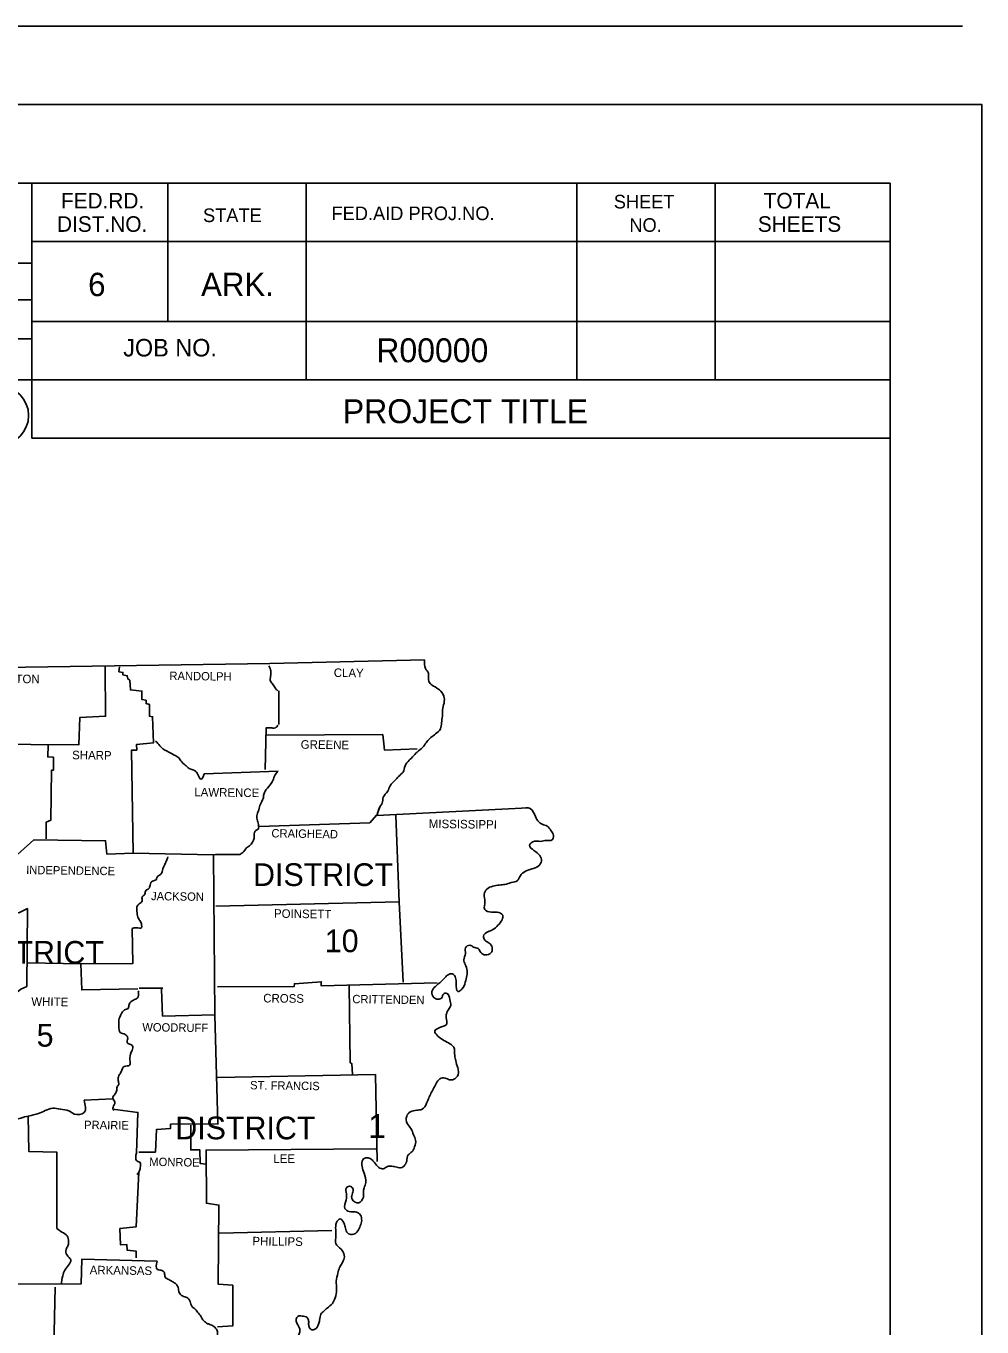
# Model space of a CAD drawing. Extents: x 23481 to 28196, y 1325020 to 1327623.
# Drawn here: x 26612 to 27092, y 1326929 to 1327582 of the extents above; entities that cross this region are included whole.
import ezdxf

# ---------------------------------------------------------------- set-up
doc = ezdxf.new("R2010")
doc.units = 0
doc.layers.add('S_ELECTRIC_UTILITIES_ANNOT', color=7, linetype='Continuous')
doc.layers.add('S_PRIMARY_CTL_ANNOT', color=7, linetype='Continuous')

msp = doc.modelspace()

# ---------------------------------------------------------------- linework, layer by layer
at = {"layer": 'S_ELECTRIC_UTILITIES_ANNOT'}
for p, q in [((27081.89, 1327581.68), (23572.11, 1327581.68)), ((27081.89, 1327542.3), (23808.34, 1327542.3)), ((23883.86, 1327502.83), (27045.67, 1327502.83)), ((26614.82, 1327502.83), (26614.82, 1327374.84)), ((26683.21, 1327502.83), (26683.21, 1327433.46)), ((26752.57, 1327502.83), (26752.57, 1327404.15)), ((26888.38, 1327502.83), (26888.38, 1327404.15)), ((26957.74, 1327502.83), (26957.74, 1327404.15)), ((27045.67, 1325448.4), (27045.67, 1327502.83)), ((27045.67, 1327473.52), (26614.82, 1327473.52)), ((27045.67, 1327473.78), (27045.67, 1327473.78)), ((26223.04, 1327462.77), (26614.82, 1327462.77)), ((26223.04, 1327444.21), (26614.82, 1327444.21)), ((27045.67, 1327433.46), (26614.82, 1327433.46)), ((26223.04, 1327424.67), (26614.82, 1327424.67)), ((27045.67, 1327404.15), (26223.04, 1327404.15)), ((26614.82, 1327374.84), (27045.67, 1327374.84)), ((26788, 1327185.58), (26789.2, 1327189.28)), ((26788.3, 1327186.78), (26789.5, 1327189.68)), ((26668.8, 1327098.98), (26680.7, 1327098.98))]:
    msp.add_line(p, q, dxfattribs=at)
for points in [[(26263.4, 1327259.08), (26425.1, 1327258.98), (26567, 1327259.28), (26734.4, 1327261.88), (26812, 1327263.68)], [(26651.7, 1327260.18), (26651.9, 1327235.38), (26638.9, 1327234.68), (26638.5, 1327221.08), (26566.2, 1327221.48)], [(26658.9, 1327260.08), (26658.6, 1327257.68), (26660.6, 1327257.38), (26660.5, 1327256.18), (26662.8, 1327255.68), (26663, 1327254.08), (26664.1, 1327253.38), (26664.4, 1327248.58), (26670.1, 1327247.98), (26670.1, 1327243.68), (26672.2, 1327243.38), (26672.2, 1327241.68), (26674, 1327241.18), (26673.9, 1327235.38), (26675.5, 1327235.08), (26675.9, 1327221.98), (26667.4, 1327221.18), (26667.5, 1327218.38), (26664.9, 1327218.28), (26665.8, 1327166.68), (26706.1, 1327165.78), (26706.8, 1327085.58), (26680.5, 1327084.88), (26680, 1327098.38)], [(26738.8, 1327248.08), (26738.8, 1327231.18)], [(26732, 1327208.68), (26732.5, 1327229.58), (26732.5, 1327225.88), (26791, 1327226.18), (26791.8, 1327218.38), (26808.3, 1327218.98)], [(26623.1, 1327220.78), (26622.9, 1327214.98), (26625.7, 1327214.78), (26625.8, 1327208.38), (26624.8, 1327208.38), (26624.4, 1327183.18), (26622.1, 1327182.18), (26622.1, 1327173.78)], [(26701.4, 1327206.48), (26738.5, 1327207.78)], [(26729, 1327180.08), (26784.5, 1327181.88), (26787.8, 1327185.68)], [(26788, 1327185.58), (26863.9, 1327189.48)], [(26797.6, 1327185.48), (26799.3, 1327142.18), (26801.3, 1327101.88)], [(26604.5, 1327163.08), (26615.9, 1327173.38), (26651.9, 1327172.88), (26652.6, 1327166.18), (26665.7, 1327166.68)], [(26719.2, 1327165.98), (26707, 1327165.98), (26706.1, 1327165.78)], [(26799.3, 1327142.18), (26707.2, 1327140.08)], [(26556.9, 1327137.08), (26608.3, 1327136.78), (26612.7, 1327138.88), (26612.4, 1327099.78), (26609.4, 1327098.48), (26606.7, 1327096.18), (26605.8, 1327095.28), (26605.7, 1327084.08), (26573, 1327084.08)], [(26665.3, 1327128.88), (26665.5, 1327111.28), (26639.5, 1327111.18), (26612.8, 1327111.68)], [(26639.5, 1327111.18), (26639.9, 1327098.08), (26668, 1327098.58)], [(26708, 1327099.58), (26746.6, 1327099.78), (26746.7, 1327101.18), (26760.1, 1327102.18), (26760.1, 1327100.08), (26818.3, 1327101.68)], [(26774.1, 1327100.08), (26774.6, 1327061.58), (26775.5, 1327060.98), (26775.8, 1327055.78)], [(26774.1, 1327100.08), (26774.6, 1327061.58), (26775.5, 1327060.98), (26775.8, 1327055.78)], [(26774.1, 1327100.08), (26774.6, 1327061.58), (26775.5, 1327060.98), (26775.8, 1327055.78)], [(26774.1, 1327100.08), (26774.6, 1327061.58), (26775.5, 1327060.98), (26775.8, 1327055.78)], [(26774.1, 1327100.08), (26774.6, 1327061.58), (26775.5, 1327060.98), (26775.8, 1327055.78)], [(26668.8, 1327097.28), (26668.3, 1327097.18)], [(26706.8, 1327085.58), (26708.3, 1327030.78), (26684.5, 1327030.68), (26684.4, 1327028.48), (26677.5, 1327028.08), (26676.9, 1327016.68), (26668.5, 1327016.68)], [(26708, 1327054.08), (26787.4, 1327055.68)], [(26787.4, 1327055.68), (26788.2, 1327011.88)], [(26787.4, 1327055.68), (26788.2, 1327011.88)], [(26787.4, 1327055.68), (26788.2, 1327011.88)], [(26787.4, 1327055.68), (26788.2, 1327011.88)], [(26787.4, 1327055.68), (26788.2, 1327011.88)], [(26787.4, 1327055.68), (26788.2, 1327011.88)], [(26787.4, 1327055.68), (26788.2, 1327011.88)], [(26787.4, 1327055.68), (26788.2, 1327011.88)], [(26641.1, 1327042.68), (26655.6, 1327043.38)], [(26613.1, 1327034.88), (26613.3, 1327016.98), (26627.4, 1327016.68), (26627.5, 1326978.28)], [(26655.6, 1327038.18), (26668.1, 1327036.58), (26667.4, 1327016.18)], [(26694.7, 1327030.18), (26694.6, 1327017.78), (26699.2, 1327017.78), (26699.4, 1327010.88), (26702.3, 1327010.58)], [(26708, 1326929.08), (26715.8, 1326929.58), (26715.7, 1326949.88), (26708.4, 1326950.38), (26708.8, 1326990.08), (26702.5, 1326990.98), (26702.3, 1327017.68), (26787.6, 1327018.28)], [(26668.5, 1327006.58), (26667.3, 1326979.18), (26659.1, 1326978.28), (26659.3, 1326970.18), (26662.6, 1326970.28), (26662.7, 1326967.48), (26667.2, 1326966.98), (26667.3, 1326963.68)], [(26709, 1326975.98), (26765.4, 1326977.38)], [(26677.7, 1326961.88), (26639.9, 1326962.88), (26639.7, 1326950.58), (26563.2, 1326950.28)], [(26626.6, 1326948.98), (26625.8, 1326911.28), (26639.7, 1326910.18)]]:
    msp.add_lwpolyline(points, dxfattribs=at)
msp.add_circle((26598.59, 1327386.27), 14.67, dxfattribs=at)
for points in [[(26812, 1327263.68), (26812.5, 1327259.28), (26813.9, 1327256.98), (26814.1, 1327252.78), (26815.8, 1327250.98), (26818.7, 1327249.18), (26821.3, 1327246.28), (26821.9, 1327242.88), (26821.1, 1327239.38), (26820.9, 1327235.48), (26820.5, 1327232.08), (26819.9, 1327228.98), (26817.5, 1327226.48), (26815.2, 1327224.68), (26813.1, 1327222.58), (26811.6, 1327220.38), (26809, 1327217.98), (26806.4, 1327215.48), (26804.3, 1327213.28), (26802.2, 1327210.48), (26801.2, 1327207.38), (26798.9, 1327205.18), (26797.1, 1327203.18), (26794.7, 1327200.48), (26793.5, 1327197.78), (26791.2, 1327194.68), (26790.7, 1327191.68), (26789.2, 1327189.28), (26789.1, 1327188.88)], [(26733.9, 1327260.58), (26734.8, 1327258.08), (26734.7, 1327255.38), (26734.7, 1327252.88), (26736, 1327251.18), (26737.3, 1327249.08), (26738.3, 1327248.18)], [(26738.4, 1327230.88), (26737.1, 1327229.58), (26734.6, 1327229.58), (26732.5, 1327229.58)], [(26677, 1327222.88), (26679.2, 1327220.58), (26681.1, 1327218.68), (26683.3, 1327217.58), (26685.9, 1327216.08), (26688.2, 1327214.88), (26689.7, 1327212.98), (26691.8, 1327210.88), (26693.9, 1327209.18), (26697.2, 1327207.58), (26698.3, 1327205.88), (26699.8, 1327203.78), (26701.4, 1327206.48)], [(26738.2, 1327207.68), (26736.7, 1327205.28), (26735.5, 1327202.48), (26733.1, 1327199.28), (26731.3, 1327196.18), (26731, 1327194.08), (26729.6, 1327191.28), (26728.8, 1327188.48), (26727.9, 1327186.08), (26727.9, 1327183.58), (26728.6, 1327181.08), (26728.4, 1327178.78), (26726.9, 1327177.68), (26726.5, 1327174.78), (26725.9, 1327172.78), (26724.6, 1327170.78), (26722.7, 1327169.28), (26720.7, 1327166.98), (26719.2, 1327165.98)], [(26862.8, 1327189.38), (26863.9, 1327189.48), (26867.3, 1327185.88), (26868.8, 1327182.88), (26871, 1327181.18), (26873.5, 1327180.28), (26875.4, 1327177.98), (26876.7, 1327175.48), (26876, 1327173.28), (26873.2, 1327173.08), (26870.1, 1327172.58), (26867.1, 1327172.68), (26864.7, 1327170.68), (26866.9, 1327167.98), (26869.8, 1327165.48), (26870.6, 1327162.78), (26869, 1327160.18), (26865.8, 1327158.78), (26862.7, 1327157.58), (26859.9, 1327155.18), (26858.6, 1327152.88), (26855.5, 1327151.88), (26852.3, 1327150.98), (26849.5, 1327150.68), (26846.3, 1327150.08), (26843.2, 1327148.58), (26841.9, 1327145.98), (26842.3, 1327142.28), (26842.2, 1327138.38), (26845.5, 1327137.08), (26848.4, 1327136.98), (26851.2, 1327135.48), (26850.9, 1327133.28), (26848.8, 1327130.48), (26846.3, 1327128.28), (26843.8, 1327127.18), (26841.5, 1327125.08), (26842.3, 1327122.98), (26844.4, 1327121.58), (26845.9, 1327119.28), (26845.7, 1327117.18), (26843.3, 1327115.68), (26840.7, 1327116.28), (26838.8, 1327118.78), (26836.6, 1327119.58), (26834.7, 1327120.48), (26832.5, 1327119.18), (26832.5, 1327116.28), (26831.7, 1327113.18), (26832.4, 1327110.88), (26833.3, 1327107.68), (26833.2, 1327105.28), (26832.4, 1327101.88), (26830.7, 1327098.38), (26828.7, 1327097.28), (26827.9, 1327101.08), (26827.5, 1327104.18), (26826.3, 1327105.98), (26824.7, 1327106.08), (26822.6, 1327104.58), (26820.3, 1327102.28), (26817.4, 1327099.78), (26815.7, 1327097.28), (26816.6, 1327094.18), (26818.8, 1327093.38), (26820.5, 1327093.98), (26821.4, 1327095.98), (26823.1, 1327096.28), (26824.7, 1327093.18)], [(26683.2, 1327164.88), (26682, 1327161.78), (26680.6, 1327158.78), (26679.7, 1327156.18), (26677.8, 1327154.68), (26677.2, 1327153.28), (26675.5, 1327152.68), (26674.2, 1327150.68), (26673.6, 1327148.88), (26672.2, 1327148.08), (26671.5, 1327145.88), (26670.2, 1327144.68), (26670.3, 1327142.68), (26668.8, 1327141.28), (26667.6, 1327139.68), (26667.6, 1327137.48), (26668.1, 1327134.58), (26669.1, 1327132.88), (26670, 1327130.68), (26669.9, 1327129.28), (26667.4, 1327129.28), (26665.3, 1327128.88)], [(26668.3, 1327097.18), (26667.8, 1327093.88), (26665.9, 1327092.98), (26663.7, 1327090.78), (26663.2, 1327088.78), (26661.4, 1327087.98), (26659.7, 1327085.88), (26658.6, 1327082.98), (26658.6, 1327079.98), (26659.3, 1327076.58), (26661.8, 1327075.68), (26663, 1327073.68), (26662.8, 1327071.58), (26665.2, 1327070.18), (26665.6, 1327068.98), (26665.2, 1327067.68), (26664.1, 1327063.98), (26664.2, 1327061.48), (26664, 1327060.38), (26661.3, 1327059.68), (26659.7, 1327056.98), (26658.6, 1327055.08), (26658.2, 1327052.58), (26658.5, 1327050.78), (26657.7, 1327049.38), (26657.4, 1327047.28), (26656.4, 1327045.48), (26655.5, 1327043.78), (26656.5, 1327041.78), (26656.2, 1327040.38), (26655.6, 1327038.18), (26656.1, 1327037.48)], [(26824.7, 1327093.18), (26825.1, 1327090.28), (26823.4, 1327087.18), (26822.8, 1327084.08), (26823.1, 1327080.98), (26819.9, 1327079.28), (26817.1, 1327077.28), (26818.7, 1327074.88), (26821.7, 1327072.68), (26824.7, 1327070.98), (26826.6, 1327069.28), (26827.1, 1327065.18), (26827.6, 1327062.58), (26828.6, 1327058.98), (26829, 1327056.48), (26827.2, 1327053.48), (26825.1, 1327052.88), (26822.9, 1327053.58), (26820.3, 1327053.78), (26818.2, 1327051.78), (26816.7, 1327048.98), (26815.2, 1327046.18), (26814.1, 1327043.78), (26813, 1327041.18), (26810.8, 1327038.18), (26808.1, 1327037.68), (26804.9, 1327036.88), (26803, 1327034.68), (26803.3, 1327030.98), (26805.1, 1327028.48), (26806.5, 1327025.38), (26807.5, 1327022.68), (26807, 1327019.28), (26805.6, 1327016.78), (26803.8, 1327015.28), (26803, 1327012.08), (26801.7, 1327009.68), (26800.5, 1327008.88), (26798.1, 1327009.08), (26795.5, 1327009.58), (26793.3, 1327009.38), (26791.2, 1327008.28), (26789.1, 1327008.98), (26786.9, 1327011.38), (26785.1, 1327013.18), (26783.1, 1327013.88), (26781, 1327012.78), (26780.6, 1327009.48), (26781.6, 1327006.08), (26782.5, 1327001.48), (26781.6, 1326998.68), (26781.3, 1326994.08)], [(26573.8, 1327038.68), (26579.4, 1327038.88), (26584.9, 1327039.08), (26588.4, 1327038.08), (26592.4, 1327036.78), (26597.1, 1327036.18), (26600.4, 1327034.88), (26604.3, 1327032.88), (26609.3, 1327033.78), (26613.2, 1327034.78), (26618.3, 1327036.08), (26621.6, 1327037.48), (26625.4, 1327038.68), (26629.2, 1327038.18), (26633.5, 1327037.38), (26636.2, 1327035.78), (26641.1, 1327036.48), (26641.1, 1327042.68)], [(26667.4, 1327016.18), (26667, 1327014.18), (26667.8, 1327012.08), (26669.2, 1327011.38), (26669.4, 1327009.38), (26668.9, 1327007.38), (26668.5, 1327006.58), (26667.6, 1327005.38)], [(26781.3, 1326994.08), (26779, 1326991.18), (26775.6, 1326992.98), (26775.6, 1326995.38), (26776.1, 1326997.88), (26774.9, 1326999.48), (26772.8, 1326998.78), (26772.8, 1326995.68), (26772.6, 1326992.68), (26772, 1326988.38), (26773.4, 1326987.08), (26776.6, 1326986.68), (26778.9, 1326986.08), (26780.3, 1326983.78), (26780.2, 1326980.98), (26779.1, 1326978.28), (26777.5, 1326976.08), (26775, 1326975.28), (26773, 1326976.58), (26772.2, 1326979.18), (26771.3, 1326981.48), (26769.6, 1326983.18), (26767.8, 1326981.28), (26767.4, 1326977.78), (26767.5, 1326974.78), (26767.5, 1326970.68), (26770.1, 1326967.98), (26771.7, 1326964.88), (26771.2, 1326962.08), (26769.3, 1326958.78), (26768.5, 1326955.88), (26767.7, 1326951.98), (26767.8, 1326947.68), (26767.1, 1326943.48), (26765.7, 1326940.68), (26763.1, 1326938.38), (26761.4, 1326936.88), (26760, 1326935.38), (26759.3, 1326932.38), (26758.8, 1326930.28), (26756.9, 1326927.78), (26755.4, 1326927.58), (26754.2, 1326928.58), (26753.8, 1326930.28), (26753.8, 1326931.98), (26753, 1326933.68), (26750.5, 1326934.38), (26748.5, 1326934.28), (26747.6, 1326932.88), (26748.9, 1326928.98), (26749.4, 1326926.48), (26748.7, 1326923.08), (26749.1, 1326922.68), (26745.5, 1326920.78), (26742.6, 1326920.48), (26740.2, 1326919.78), (26737.9, 1326918.28), (26736.8, 1326916.08), (26735.2, 1326914.28), (26733.8, 1326912.58), (26731.9, 1326911.78), (26729.8, 1326912.18), (26727, 1326912.48), (26725.4, 1326910.48), (26725.9, 1326907.58), (26727.8, 1326905.88), (26730.6, 1326905.08), (26733.5, 1326905.28), (26736.3, 1326905.58), (26738.9, 1326904.18), (26738.4, 1326901.48), (26735.9, 1326900.18), (26732.2, 1326899.78), (26729.2, 1326900.08), (26725.6, 1326899.28), (26723.8, 1326896.98), (26724.8, 1326893.48), (26728.7, 1326892.08), (26730.5, 1326888.78), (26730.6, 1326885.68), (26729.3, 1326881.58), (26727.5, 1326879.68), (26724, 1326878.88), (26721.3, 1326878.38), (26720.9, 1326873.78), (26719.7, 1326871.48), (26717.6, 1326870.78), (26714.6, 1326872.28), (26712.8, 1326872.98), (26710.6, 1326873.98), (26707.8, 1326875.68), (26705.7, 1326875.38), (26706.3, 1326870.98), (26706.5, 1326870.78), (26708.9, 1326867.48), (26711.3, 1326864.88), (26712.4, 1326861.78)], [(26627.5, 1326978.28), (26630, 1326976.58), (26632.6, 1326974.58), (26633.3, 1326971.88), (26633.1, 1326969.98), (26632.3, 1326968.38), (26632.1, 1326965.88), (26633.3, 1326964.08), (26634.4, 1326962.58), (26633.3, 1326959.88), (26631.4, 1326957.38), (26630.4, 1326954.58), (26629.7, 1326950.38)], [(26677.7, 1326961.88), (26678, 1326957.78), (26680.4, 1326957.18), (26681.4, 1326956.08), (26681.9, 1326953.78), (26683.6, 1326952.78), (26685.9, 1326951.38), (26687.3, 1326950.38), (26688.3, 1326948.78), (26688.9, 1326946.18), (26690.5, 1326944.48), (26692.7, 1326943.68), (26694.3, 1326941.78), (26695.3, 1326939.08), (26696.9, 1326937.88), (26698.5, 1326935.78), (26699.3, 1326934.88), (26700.7, 1326932.48), (26702.1, 1326931.28), (26703.1, 1326930.58), (26704.7, 1326930.08), (26706.7, 1326928.78), (26708, 1326926.78), (26708, 1326925.28), (26707.5, 1326922.98), (26707.1, 1326920.58), (26706.9, 1326917.88), (26706.7, 1326915.48), (26707.6, 1326913.48), (26707.1, 1326910.48), (26706.1, 1326908.88), (26706, 1326906.68), (26705.7, 1326903.38), (26705.3, 1326901.48), (26704.4, 1326898.38), (26703.1, 1326896.78)]]:
    msp.add_spline(points, degree=3, dxfattribs=at)
at = {"layer": 'S_PRIMARY_CTL_ANNOT'}
msp.add_lwpolyline([(23808.34, 1327542.3), (27091.73, 1327542.3), (27091.73, 1325408.97), (23808.34, 1325408.97)], close=True, dxfattribs=at)

# ---------------------------------------------------------------- texts
at = {"layer": 'S_ELECTRIC_UTILITIES_ANNOT'}
for s, height, p in [('TOTAL', 7.82, (26982.17, 1327490.13)), ('FED.RD.', 7.82, (26629.47, 1327490.13)), ('SHEET', 6.841, (26906.94, 1327490.13)), ('DIST.NO.', 7.82, (26627.52, 1327478.41)), ('STATE', 6.841, (26700.79, 1327483.29)), ('FED.AID PROJ.NO.', 6.8407, (26765.28, 1327484.27)), ('NO.', 6.841, (26914.76, 1327478.41)), ('SHEETS', 7.82, (26979.24, 1327478.41)), ('6', 11.72, (26643.15, 1327446.16)), ('ARK.', 11.724, (26699.82, 1327446.16)), ('JOB NO.', 8.793, (26660.74, 1327415.88)), ('R00000', 12, (26787.77, 1327412.98)), ('PROJECT TITLE', 12, (26770.98, 1327382.41)), ('DISTRICT', 11.4, (26725.9, 1327150.18)), ('10', 11.4, (26761.92, 1327116.98)), ('DISTRICT', 11.4, (26580.75, 1327111.19)), ('5', 11.4, (26617.3, 1327069.58)), ('DISTRICT', 11.4, (26686.9, 1327023.08)), ('1', 12, (26783.7, 1327023.78))]:
    msp.add_text(s, height=height, dxfattribs=at).set_placement(p)
for s, height, rotation, p in [('RANDOLPH', 4.201, 359.25835, (26683.9, 1327253.58)), ('CLAY', 4.299, 359.22578, (26766.4, 1327255.08)), ('FULTON', 4.3, 359.49961, (26595.8, 1327252.08)), ('SHARP', 4.3, 359.39049, (26635.1, 1327213.78)), ('GREENE', 4.301, 359.2361, (26749.8, 1327219.08)), ('LAWRENCE', 4.301, 359.26783, (26696.4, 1327195.18)), ('CRAIGHEAD', 4.201, 359.11588, (26735.1, 1327174.58)), ('MISSISSIPPI', 4.2995, 359.30972, (26814.1, 1327179.28)), ('INDEPENDENCE', 4.1993, 359.21874, (26612, 1327156.18)), ('JACKSON', 4.199, 359.13523, (26674.7, 1327143.08)), ('POINSETT', 4.3, 359.19871, (26736.4, 1327134.28)), ('WHITE', 4.301, 359.31386, (26614.6, 1327090.08)), ('CROSS', 4.3, 359.38394, (26731, 1327091.78)), ('CRITTENDEN', 4.201, 359.21302, (26775.7, 1327091.38)), ('WOODRUFF', 4.199, 359.27478, (26670.3, 1327077.28)), ('ST. FRANCIS', 4.1993, 359.22157, (26724.4, 1327048.18)), ('PRAIRIE', 4.2, 359.21158, (26641.1, 1327028.28)), ('LEE', 4.301, 359.43273, (26736.1, 1327011.28)), ('MONROE', 4.199, 359.03308, (26673.8, 1327009.78)), ('PHILLIPS', 4.3, 359.31794, (26725.6, 1326969.88)), ('ARKANSAS', 4.3, 359.26783, (26643.9, 1326955.38))]:
    msp.add_text(s, height=height, rotation=rotation, dxfattribs=at).set_placement(p)

doc.saveas('drawing.dxf')
